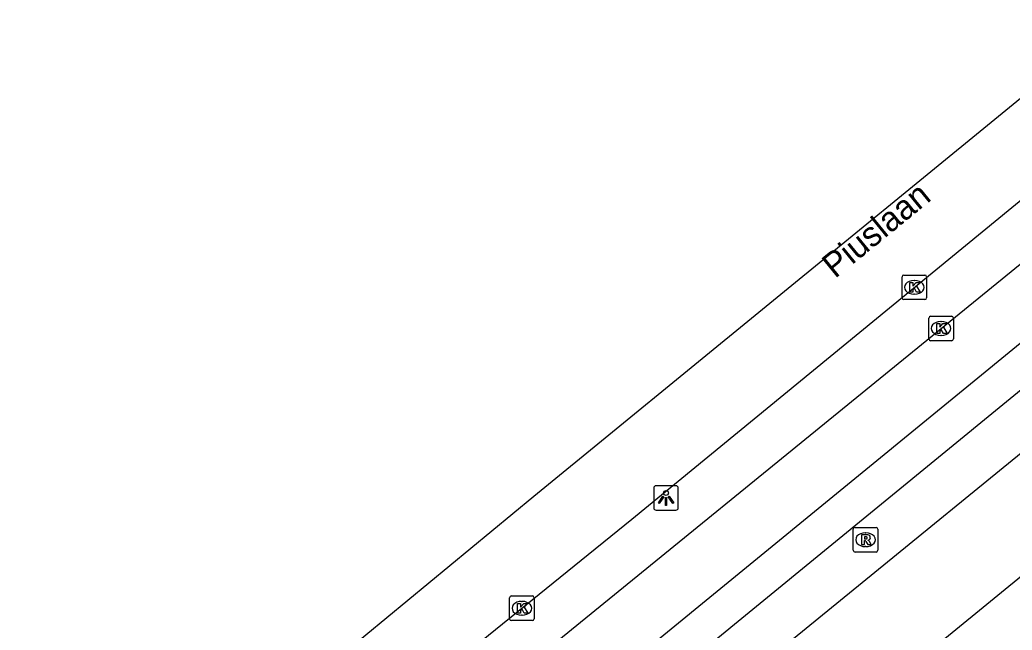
# Model space of a CAD drawing. Extents: x 162532 to 163264, y 381233 to 382042.
# Drawn here: x 162603.37 to 162643.76, y 381899.47 to 381924.29 of the extents above; entities that cross this region are included whole.
import ezdxf

# ---------------------------------------------------------------- set-up
doc = ezdxf.new("R2010")
doc.units = 0
for name, color, linetype in [('IMGEO_Kolk', 7, 'Continuous'), ('IMGEO_Lichtpunt', 7, 'Continuous'), ('IMGEO_Openbare_ruimte_label', 7, 'Continuous'), ('IMGEO_Rijbaan_lokaal_gesloten', 7, 'Continuous'), ('IMGEO_Rijbaan_lokaal_open', 7, 'Continuous'), ('IMGEO_Rijbaan_regionaal_gesloten', 7, 'Continuous'), ('IMGEO_Rioolput', 7, 'Continuous'), ('IMGEO_Voetpad_open', 7, 'Continuous')]:
    doc.layers.add(name, color=color, linetype=linetype)

msp = doc.modelspace()

# ---------------------------------------------------------------- linework, layer by layer
at = {"layer": 'IMGEO_Kolk'}
for p, q in [((162639.28, 381912.986), (162639.28, 381913.838)), ((162639.355, 381913.912), (162640.207, 381913.912)), ((162640.281, 381913.838), (162640.281, 381912.986)), ((162639.768, 381913.692), (162639.793, 381913.692)), ((162639.791, 381913.132), (162639.766, 381913.132)), ((162640.207, 381912.912), (162639.355, 381912.912)), ((162640.445, 381912.239), (162641.297, 381912.239)), ((162640.37, 381911.313), (162640.37, 381912.165)), ((162640.858, 381912.019), (162640.883, 381912.019)), ((162641.371, 381912.165), (162641.371, 381911.313)), ((162640.881, 381911.459), (162640.856, 381911.459)), ((162641.297, 381911.239), (162640.445, 381911.239)), ((162623.303, 381899.93), (162623.303, 381900.782)), ((162623.378, 381900.856), (162624.23, 381900.856)), ((162623.791, 381900.636), (162623.816, 381900.636)), ((162624.304, 381900.782), (162624.304, 381899.93)), ((162624.23, 381899.856), (162623.378, 381899.856)), ((162623.814, 381900.076), (162623.789, 381900.076))]:
    msp.add_line(p, q, dxfattribs=at)
for points in [[(162639.28, 381912.986), (162639.28, 381913.838)], [(162639.355, 381913.912), (162640.207, 381913.912)], [(162640.281, 381913.838), (162640.281, 381912.986)], [(162639.601, 381913.612), (162639.724, 381913.612), (162639.724, 381913.461), (162639.854, 381913.612), (162640.018, 381913.612), (162639.872, 381913.461), (162640.025, 381913.212), (162639.873, 381913.212), (162639.788, 381913.376), (162639.724, 381913.309), (162639.724, 381913.212), (162639.601, 381913.212), (162639.601, 381913.612)], [(162640.207, 381912.912), (162639.355, 381912.912)], [(162640.445, 381912.239), (162641.297, 381912.239)], [(162640.37, 381911.313), (162640.37, 381912.165)], [(162640.691, 381911.939), (162640.814, 381911.939), (162640.814, 381911.788), (162640.944, 381911.939), (162641.108, 381911.939), (162640.962, 381911.788), (162641.115, 381911.539), (162640.963, 381911.539), (162640.878, 381911.703), (162640.814, 381911.636), (162640.814, 381911.539), (162640.691, 381911.539), (162640.691, 381911.939)], [(162641.371, 381912.165), (162641.371, 381911.313)], [(162641.297, 381911.239), (162640.445, 381911.239)], [(162623.303, 381899.93), (162623.303, 381900.782)], [(162623.378, 381900.856), (162624.23, 381900.856)], [(162623.624, 381900.556), (162623.747, 381900.556), (162623.747, 381900.405), (162623.877, 381900.556), (162624.041, 381900.556), (162623.895, 381900.405), (162624.048, 381900.156), (162623.896, 381900.156), (162623.811, 381900.32), (162623.747, 381900.253), (162623.747, 381900.156), (162623.624, 381900.156), (162623.624, 381900.556)], [(162624.304, 381900.782), (162624.304, 381899.93)], [(162624.23, 381899.856), (162623.378, 381899.856)]]:
    msp.add_lwpolyline(points, dxfattribs=at)
for centre, start, end in [((162639.357, 381913.836), 91.552, 178.448), ((162639.357, 381913.836), 91.552, 178.448), ((162640.205, 381913.836), 1.552, 88.448), ((162640.205, 381913.836), 1.552, 88.448), ((162639.357, 381912.988), 181.552, 268.448), ((162639.357, 381912.988), 181.552, 268.448), ((162640.205, 381912.988), 271.552, 358.448), ((162640.205, 381912.988), 271.552, 358.448), ((162640.447, 381912.163), 91.552, 178.448), ((162640.447, 381912.163), 91.552, 178.448), ((162641.295, 381912.163), 1.552, 88.448), ((162641.295, 381912.163), 1.552, 88.448), ((162640.447, 381911.315), 181.552, 268.448), ((162640.447, 381911.315), 181.552, 268.448), ((162641.295, 381911.315), 271.552, 358.448), ((162641.295, 381911.315), 271.552, 358.448), ((162623.38, 381900.78), 91.552, 178.448), ((162623.38, 381900.78), 91.552, 178.448), ((162624.228, 381900.78), 1.552, 88.448), ((162624.228, 381900.78), 1.552, 88.448), ((162623.38, 381899.932), 181.552, 268.448), ((162623.38, 381899.932), 181.552, 268.448), ((162624.228, 381899.932), 271.552, 358.448), ((162624.228, 381899.932), 271.552, 358.448)]:
    msp.add_arc(centre, 0.0765, start, end, dxfattribs=at)
for centre, major_axis, ratio, start_param, end_param in [((162639.767, 381913.412), (-0.387, 0.002), 0.722429, 4.712389, 7.853982), ((162639.792, 381913.412), (-0.39, 0.002), 0.717154, 1.570796, 4.712389), ((162640.857, 381911.739), (-0.387, 0.002), 0.722429, 4.712389, 7.853982), ((162640.882, 381911.739), (-0.39, 0.002), 0.717154, 1.570796, 4.712389), ((162623.79, 381900.356), (-0.387, 0.002), 0.722429, 4.712389, 7.853982), ((162623.815, 381900.356), (-0.39, 0.002), 0.717154, 1.570796, 4.712389)]:
    msp.add_ellipse(centre, major_axis=major_axis, ratio=ratio, start_param=start_param, end_param=end_param, dxfattribs=at)
at = {"layer": 'IMGEO_Lichtpunt'}
for p, q in [((162630.075, 381905.344), (162629.267, 381905.344)), ((162630.075, 381905.344), (162629.267, 381905.344)), ((162629.173, 381905.249), (162629.173, 381904.442)), ((162629.173, 381905.249), (162629.173, 381904.442)), ((162630.169, 381904.442), (162630.169, 381905.249)), ((162630.169, 381904.442), (162630.169, 381905.249)), ((162629.267, 381904.348), (162630.075, 381904.348)), ((162629.267, 381904.348), (162630.075, 381904.348))]:
    msp.add_line(p, q, dxfattribs=at)
for points in [[(162629.547, 381904.913), (162629.586, 381904.885), (162629.398, 381904.623), (162629.36, 381904.65), (162629.547, 381904.913)], [(162629.649, 381904.865), (162629.696, 381904.865), (162629.696, 381904.543), (162629.649, 381904.543), (162629.649, 381904.865)], [(162629.759, 381904.885), (162629.797, 381904.912), (162629.984, 381904.65), (162629.945, 381904.622), (162629.759, 381904.885)]]:
    msp.add_lwpolyline(points, dxfattribs=at)
msp.add_circle((162629.672, 381905.047), 0.0994, dxfattribs=at)
for centre, start, end in [((162629.267, 381905.249), 90, 180), ((162629.267, 381905.249), 90, 180), ((162630.075, 381905.249), 0, 90), ((162630.075, 381905.249), 0, 90), ((162629.267, 381904.442), 180, 270), ((162629.267, 381904.442), 180, 270), ((162630.075, 381904.442), 270, 0), ((162630.075, 381904.442), 270, 360)]:
    msp.add_arc(centre, 0.0946, start, end, dxfattribs=at)
at = {"layer": 'IMGEO_Rijbaan_lokaal_gesloten'}
for points in [[(162734.879, 381983.414), (162719.334, 381970.721), (162660.667, 381922.782), (162621.159, 381890.444), (162606.537, 381878.623)], [(162690.659, 381949.234), (162620.312, 381891.687), (162605.631, 381879.753)]]:
    msp.add_lwpolyline(points, dxfattribs=at)
at = {"layer": 'IMGEO_Rijbaan_lokaal_open'}
msp.add_lwpolyline([(162603.985, 381881.713), (162607.58, 381884.559), (162623.559, 381897.652), (162657.024, 381924.879), (162674.516, 381939.191), (162688.899, 381951.026), (162689.109, 381951.165)], dxfattribs=at)
at = {"layer": 'IMGEO_Rijbaan_regionaal_gesloten'}
for points in [[(162536.507, 381827.181), (162540.157, 381830.785), (162552.383, 381842.71), (162567.001, 381856.379), (162572.096, 381861.048), (162587.252, 381874.266), (162599.477, 381884.467), (162624.285, 381904.911), (162662.123, 381935.842), (162667.509, 381940.274), (162683.823, 381953.589), (162710.356, 381975.317), (162716.011, 381979.972), (162720.796, 381983.875), (162725.296, 381987.518), (162732.266, 381992.774), (162738.678, 381997.54), (162745.062, 382002.248), (162751.538, 382007.048), (162758.019, 382011.857), (162764.398, 382016.604), (162770.791, 382021.331), (162777.282, 382026.141), (162780.539, 382028.529)], [(162562.147, 381847.417), (162563.048, 381848.267), (162568.79, 381853.73), (162570.541, 381855.349), (162576.654, 381860.802), (162581.631, 381865.192), (162587.814, 381870.584), (162593.659, 381875.675), (162600.282, 381881.209), (162616.901, 381894.769), (162628.275, 381903.978), (162646.842, 381919.202), (162662.907, 381932.358), (162665.643, 381934.608), (162671.529, 381939.448), (162680.739, 381946.928), (162688.64, 381953.42), (162696.581, 381959.932), (162705.643, 381967.393), (162712.504, 381972.937), (162718.866, 381978.131), (162722.177, 381980.799), (162726.008, 381983.557)]]:
    msp.add_lwpolyline(points, dxfattribs=at)
at = {"layer": 'IMGEO_Rioolput'}
for p, q in [((162637.294, 381902.719), (162637.294, 381903.571)), ((162637.369, 381903.645), (162638.221, 381903.645)), ((162637.782, 381903.425), (162637.807, 381903.425)), ((162638.295, 381903.571), (162638.295, 381902.719)), ((162638.221, 381902.645), (162637.369, 381902.645)), ((162637.805, 381902.865), (162637.78, 381902.865))]:
    msp.add_line(p, q, dxfattribs=at)
for points in [[(162637.294, 381902.719), (162637.294, 381903.571)], [(162637.369, 381903.645), (162638.221, 381903.645)], [(162637.883, 381903.343), (162637.631, 381903.345), (162637.631, 381902.945)], [(162638.295, 381903.571), (162638.295, 381902.719)], [(162637.631, 381902.945), (162637.755, 381902.945), (162637.755, 381903.107), (162637.766, 381903.107)], [(162637.809, 381903.264), (162637.755, 381903.264), (162637.755, 381903.183)], [(162637.755, 381903.183), (162637.807, 381903.183)], [(162637.813, 381903.078), (162637.884, 381902.945), (162638.024, 381902.945), (162637.959, 381903.071)], [(162638.221, 381902.645), (162637.369, 381902.645)]]:
    msp.add_lwpolyline(points, dxfattribs=at)
for centre, radius, start, end in [((162637.371, 381903.569), 0.0765, 91.552, 178.448), ((162637.371, 381903.569), 0.0765, 91.552, 178.448), ((162637.882, 381903.233), 0.109, 350.3612, 89.416), ((162638.219, 381903.569), 0.0765, 1.552, 88.448), ((162638.219, 381903.569), 0.0765, 1.552, 88.448), ((162637.765, 381903.054), 0.0533, 26.0293, 88.6989), ((162637.791, 381903.372), 0.19, 274.7715, 282.9687), ((162637.815, 381903.168), 0.0964, 77.0061, 93.1865), ((162637.829, 381903.225), 0.0378, 276.6634, 79.6772), ((162637.88, 381903.233), 0.112, 277.5842, 350.9817), ((162637.864, 381903.018), 0.108, 29.5134, 73.7905), ((162637.371, 381902.721), 0.0765, 181.552, 268.448), ((162637.371, 381902.721), 0.0765, 181.552, 268.448), ((162638.219, 381902.721), 0.0765, 271.552, 358.448), ((162638.219, 381902.721), 0.0765, 271.552, 358.448)]:
    msp.add_arc(centre, radius, start, end, dxfattribs=at)
for centre, major_axis, ratio, start_param, end_param in [((162637.781, 381903.145), (-0.387, 0.002), 0.722429, 4.712389, 7.853982), ((162637.806, 381903.145), (-0.39, 0.002), 0.717154, 1.570796, 4.712389)]:
    msp.add_ellipse(centre, major_axis=major_axis, ratio=ratio, start_param=start_param, end_param=end_param, dxfattribs=at)
at = {"layer": 'IMGEO_Voetpad_open'}
for points in [[(162733.629, 381980.885), (162733.544, 381980.135), (162733.168, 381979.496), (162726.796, 381974.271), (162710.873, 381961.232), (162692.562, 381946.284), (162678.17, 381934.546), (162660.687, 381920.23), (162645.534, 381907.811), (162628.02, 381893.546), (162627.054, 381892.753)], [(162629.198, 381889.473), (162658.271, 381913.213)]]:
    msp.add_lwpolyline(points, dxfattribs=at)

# ---------------------------------------------------------------- texts
at = {"layer": 'IMGEO_Openbare_ruimte_label'}
msp.add_text('Piuslaan', height=1, rotation=39.1967, dxfattribs=at).set_placement((162636.55, 381913.749))

doc.saveas('drawing.dxf')
